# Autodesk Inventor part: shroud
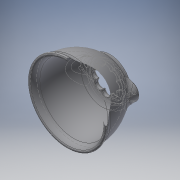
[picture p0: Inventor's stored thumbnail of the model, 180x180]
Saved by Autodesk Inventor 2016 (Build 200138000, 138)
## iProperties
Created: 2015-05
Part Number: shroud
Material: Generic
Document SubType Name: Modeling
Designer: Brent
Density: 1 g/cm^3
Appearance: Default
Author: Brent
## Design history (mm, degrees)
sketch "Sketch1"
  geometry: C1 r 12.27 at (0, 0); C2 r 2.667 at (5.388, 5.388) reference; C3 r 2.667 at (7.62, 0) reference; C4 r 2.667 at (5.388, -5.388) reference; C5 r 2.667 at (0, -7.62) reference; C6 r 2.667 at (-5.388, -5.388) reference; C7 r 2.667 at (-7.62, 0) reference; C8 r 2.667 at (-5.388, 5.388) reference; C9 r 2.667 at (0, 7.62) reference; A1 r 2.947 centre (5.388, 5.388) between (7.615, 3.458) and (3.458, 7.615); A2 r 2.941 centre (7.62, 0) between (7.832, -2.934) and (7.832, 2.934); A3 r 2.947 centre (5.388, -5.388) between (3.458, -7.615) and (7.615, -3.458); A4 r 2.941 centre (0, -7.62) between (-2.934, -7.832) and (2.934, -7.832); A5 r 2.947 centre (-5.388, -5.388) between (-7.615, -3.458) and (-3.458, -7.615); A6 r 2.941 centre (-7.62, 0) between (-7.832, 2.934) and (-7.832, -2.934); A7 r 2.947 centre (-5.388, 5.388) between (-3.458, 7.615) and (-7.615, 3.458); A8 r 2.941 centre (0, 7.62) between (2.934, 7.832) and (-2.934, 7.832); A9 r 10.561 centre (0, 0) between (7.313, -7.62) and (7.62, -7.313); A10 r 10.561 centre (0, 0) between (-7.62, -7.313) and (-7.313, -7.62); A11 r 10.561 centre (0, 0) between (7.62, 7.313) and (7.313, 7.62); A12 r 10.561 centre (0, 0) between (-7.313, 7.62) and (-7.62, 7.313); A13 r 0.318 centre (-7.855, 3.25) between (-7.832, 2.934) and (-7.615, 3.458); A14 r 0.318 centre (-7.855, -3.25) between (-7.615, -3.458) and (-7.832, -2.934); A15 r 0.318 centre (-3.25, -7.855) between (-2.934, -7.832) and (-3.458, -7.615); A16 r 0.317 centre (3.25, -7.855) between (3.458, -7.615) and (2.934, -7.832); A17 r 0.318 centre (7.855, -3.25) between (7.832, -2.934) and (7.615, -3.458); A18 r 0.318 centre (7.855, 3.25) between (7.615, 3.458) and (7.832, 2.934); A19 r 0.318 centre (3.25, 7.855) between (2.934, 7.832) and (3.458, 7.615); A20 r 0.318 centre (-3.25, 7.855) between (-3.458, 7.615) and (-2.934, 7.832); 1 further point
  constraints: 48 point on circle, 21 centre point, 16 tangent, 10 coincident, 7 equal radius
  dimensions: "d0" = 0.3175 radius of A13
extrude "Extrusion1" new body sketch "Sketch1" distance "d1" = 3.175; taper "d2" = 0 deg
sketch "Sketch2"
  geometry: L1 (0, 11.308)-(-0.992, 11.308); L2 (-0.992, 11.308)-(-0.992, 13.654); L3 (-0.992, 13.654)-(0, 13.654); L4 (0, 13.654)-(0, 11.308); 1 further point
  constraints: 8 end point, 2 parallel, 1 horizontal, 1 perpendicular
extrude "Extrusion2" join sketch "Sketch2" distance "d3" = 3.175; taper "d4" = 0 deg
sketch "Sketch3"
  geometry: L1 (3.175, 0)-(0, 0) reference; L2 (3.175, 1.384)-(3.175, 0) reference; L3 (0, 1.384)-(3.175, 1.384) reference; L4 (0, 1.384)-(0, 0) reference; L5 (0, 1.384)-(0, 0) reference; L6 (0, 1.384)-(3.175, 1.384) reference; L7 (-30.25, 16.458)-(-28.775, 18.195); L8 (3.175, -12.27)-(-30.25, -12.27); A1 r 29.45 centre (-24.818, -15.854) between (0, 0) and (-24.479, 13.594); A2 r 7.418 centre (-24.394, 21.011) between (-30.25, 16.458) and (-24.479, 13.594); A3 r 36.291 centre (-25.939, -20.282) between (3.175, 1.384) and (-24.549, 15.982); A4 r 5.552 centre (-24.336, 21.53) between (-28.775, 18.195) and (-24.549, 15.982)
  constraints: 8 point on circle, 4 centre point, 4 end point, 2 tangent, 1 horizontal
revolve "Revolution1" sketch "Sketch3" stored, may be unused: angle "d5" = 90 deg
sketch "Sketch4"
  geometry: L1 (0.992, 13.654)-(0, 13.654) reference; C1 r 12.27 at (0, 0); C2 r 15.891 at (0, 0); A1 r 13.654 centre (0, 0) between (0, 13.654) and (0.992, 13.618) reference; 1 further point
  constraints: 2 centre point, 2 coincident
extrude "Extrusion3" join sketch "Sketch4" distance "d6" = 3.175; taper "d7" = 0 deg
fillet "Fillet1" dims "d8" = 11.1125
fillet "Fillet2" dims "d9" = 0.3556
fillet "Fillet3" dims "d10" = 1.27
sketch "Sketch5"
  geometry: C1 r 15.891 at (0, 0) reference; C2 r 12.839 at (0, 0); C3 r 14.574 at (0, 0); A1 r 2.947 centre (5.388, -5.388) between (3.458, -7.615) and (7.615, -3.458) reference; A2 r 0.318 centre (3.25, -7.855) between (3.458, -7.615) and (2.934, -7.832) reference; A3 r 2.941 centre (0, -7.62) between (-2.934, -7.832) and (2.934, -7.832) reference; A4 r 0.317 centre (-3.25, -7.855) between (-2.934, -7.832) and (-3.458, -7.615) reference; A5 r 2.947 centre (-5.388, -5.388) between (-7.615, -3.458) and (-3.458, -7.615) reference; A6 r 0.318 centre (-7.855, -3.25) between (-7.615, -3.458) and (-7.832, -2.934) reference; A7 r 2.941 centre (-7.62, 0) between (-7.832, 2.934) and (-7.832, -2.934) reference; A8 r 0.318 centre (-7.855, 3.25) between (-7.832, 2.934) and (-7.615, 3.458) reference; A9 r 2.947 centre (-5.388, 5.388) between (-3.458, 7.615) and (-7.615, 3.458) reference; A10 r 0.318 centre (-3.25, 7.855) between (-3.458, 7.615) and (-2.934, 7.832) reference; A11 r 2.941 centre (0, 7.62) between (2.934, 7.832) and (-2.934, 7.832) reference; A12 r 0.318 centre (3.25, 7.855) between (2.934, 7.832) and (3.458, 7.615) reference; A13 r 2.947 centre (5.388, 5.388) between (7.615, 3.458) and (3.458, 7.615) reference; A14 r 0.318 centre (7.855, 3.25) between (7.615, 3.458) and (7.832, 2.934) reference; A15 r 2.941 centre (7.62, 0) between (7.832, -2.934) and (7.832, 2.934) reference; A16 r 0.318 centre (7.855, -3.25) between (7.832, -2.934) and (7.615, -3.458) reference; 1 further point
  constraints: 2 centre point, 2 coincident
extrude "Extrusion4" cut sketch "Sketch5" distance "d11" = 3.175; taper "d12" = 0 deg
sketch "Sketch6"
  geometry: L1 (22.392, 6.705)-(22.392, -6.705); L2 (-22.392, -6.705)-(-22.392, 6.705); L3 (-22.392, 6.705)-(-14.406, 6.705); L4 (-14.406, -6.705)-(-22.392, -6.705); L5 (22.392, -6.705)-(14.406, -6.705); L6 (14.406, 6.705)-(22.392, 6.705); C1 r 14.574 at (0, 0) reference; A1 r 15.891 centre (0, 0) between (-14.406, 6.705) and (-14.406, -6.705) reference; 1 further point
  constraints: 12 end point, 5 parallel, 4 point on circle, 2 horizontal, 2 perpendicular
extrude "Extrusion5" join sketch "Sketch6" distance "d13" = 11.1125; taper "d14" = 0 deg
delete_face "Delete Face1"
delete_face "Delete Face2"
fillet "Fillet4" dims "d15" = 6.70549
sketch "Sketch7"
  geometry: C1 r 1.207 at (-18.088, 0); C2 r 1.207 at (17.994, 0); 1 further point
  constraints: 2 centre point
  dimensions: "d16" = 2.413 diameter of C1; "d17" = 2.413 diameter of C2
extrude "Extrusion6" cut sketch "Sketch7" distance "d18" = 4.7625; taper "d19" = 0 deg
chamfer "Chamfer1" distance "d20" = 0.508; stored, may be unused: second distance "d21" = 3.175, angle "d22" = 45 deg
fillet "Fillet5" dims "d23" = 6.70549
chamfer "Chamfer3" distance "d27" = 0.508; stored, may be unused: second distance "d28" = 3.175, angle "d29" = 45 deg
fillet "Fillet6" dims "d30" = 1.016
body "Solid1"
node "Reference1"
node "Reference2"
node "Reference3"
node "Reference4"
node "Reference5"
node "Reference6"
node "Reference7"
node "Reference8"
node "Projected Loop1"
node "Projected Loop2"
node "Projected Loop3"
